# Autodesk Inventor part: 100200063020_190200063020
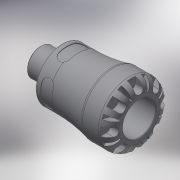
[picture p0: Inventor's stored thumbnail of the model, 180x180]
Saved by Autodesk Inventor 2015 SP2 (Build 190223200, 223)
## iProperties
Created: 2016-12
Part Number: 100200063020_190200063020
Material: Generic
Description: PLASSON MALE ADAPTOR 63X2" SERIES 1
Document SubType Name: Modeling
Designer: KIM
Mass: 447.839 g
Surface Area: 722.341 cm^2
Volume: 447.839 cm^3
Density: 1 g/cm^3
Appearance: Default
Author: KIM
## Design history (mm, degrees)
derived "1002.ipt"
feature "Solid1::1002.ipt"
tag "TaggingFeature1"
body "Solid1"
other parameters: "d0" = 129, "d1" = 38.64, "d2" = 63, "d3" = 78.75, "d4" = 103, "d6" = 92, "d8" = 87.55, "d13" = 9.7, "d14" = 9.7, "d15" = 0, "d17" = 360 deg, "d19" = 8 deg, "d20" = 1.26, "d21" = 1.26, "d22" = 8 deg, "d24" = 0, "d26" = 360 deg, "d32" = 0.925, "d33" = 10.3, "d34" = 59.614, "d35" = 7.875, "d38" = 25, "d39" = 1.78842, "d42" = 22.05, "d43" = 14.49, "d45" = 19.012, "d46" = 0, "d59" = 360 deg, "d61" = 18.7425, "d62" = 1.26, "d64" = 0, "d65" = 1.03, "d_" = 63, "E_" = 103, "H_" = 129, "l_" = 92, "R_" = 59.614, "l_2" = 25, "d9" = 12.125, "d11" = 103, "d12" = 78.75
